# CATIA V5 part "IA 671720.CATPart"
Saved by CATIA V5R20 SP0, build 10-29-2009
Part number: IA 671720
Revision: ANY
Definition: UNKNOWN
Nomenclature: IA 671720
Source: Unknown
Bounding box of the stored display mesh (mm): x -3.35 to 3.35, y -7.95 to 9.02, z -3.186 to 3.186
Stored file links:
  C:\Users\Utente\Desktop\IO LAVORO\3D X SITO CF\CUMSA\3D files IA\IA 671720\IA 671720.CATPart
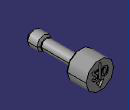
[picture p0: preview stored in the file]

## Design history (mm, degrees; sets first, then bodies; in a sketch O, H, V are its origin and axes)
Body1 "Cortar-Extruir4" (main body)
  Solid1: solid without history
